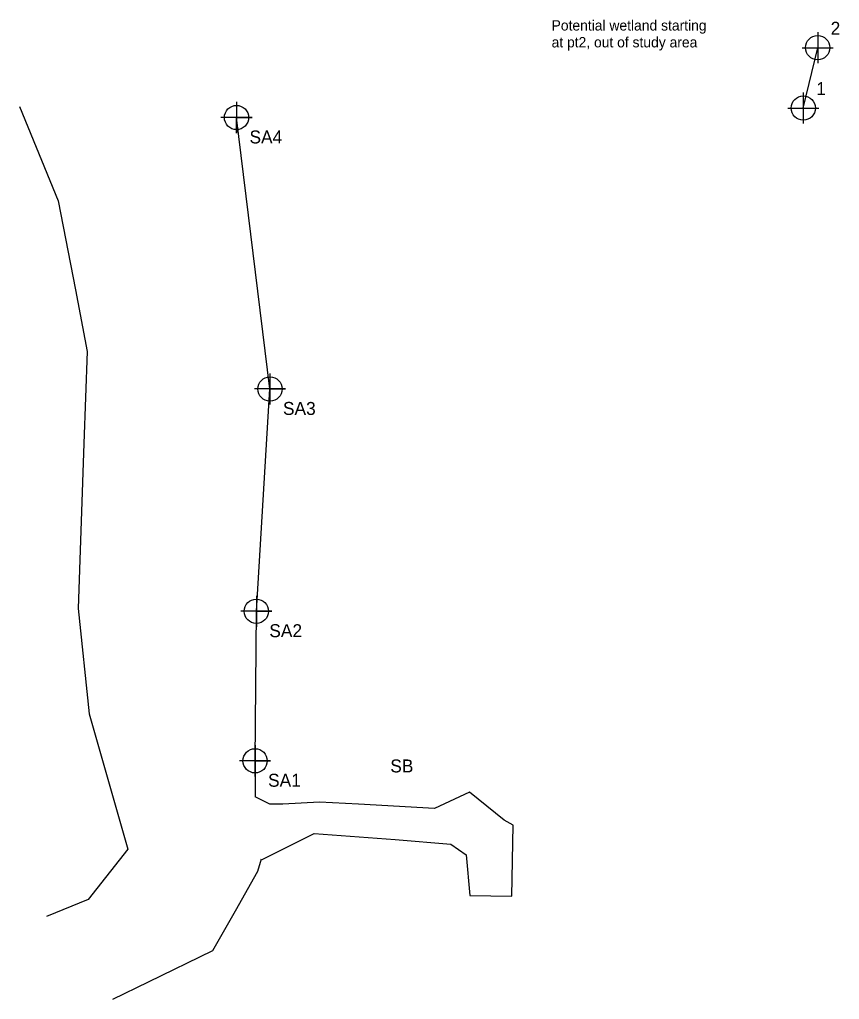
# Model space of a CAD drawing. Extents: x 2159473 to 2159631, y 1006206 to 1006395.
import ezdxf

# ---------------------------------------------------------------- set-up
doc = ezdxf.new("R2010")
doc.units = 0
for name, color, linetype in [('COGO Default Chain', 7, 'Continuous'), ('Cogo Default Point CELL', 7, 'Continuous'), ('COGO Default Point Number', 7, 'Continuous'), ('Exist Hydro Jurisdictional Stream or Body of Water NEU Mitigable', 7, 'Continuous'), ('Exist Hydro Jurisdictional Stream or Body of Water NEU Mitigable Cogo Comment', 7, 'Continuous'), ('Exist Hydro Jurisdictional Stream or Body of Water NEU Mitigable Cogo Point CELL', 7, 'Continuous'), ('Exist Hydro Jurisdictional Stream or Body of Water NEU NonMitigable', 7, 'Continuous')]:
    doc.layers.add(name, color=color, linetype=linetype)

msp = doc.modelspace()

# ---------------------------------------------------------------- linework, layer by layer
at = {"layer": 'COGO Default Chain'}
msp.add_line((2159623.64, 1006377.7), (2159626.42, 1006389.34), dxfattribs=at)
at = {"layer": 'Cogo Default Point CELL'}
for points in [[(2159626.42, 1006392.34), (2159626.42, 1006389.34)], [(2159623.42, 1006389.34), (2159626.42, 1006389.34)], [(2159626.42, 1006389.34), (2159629.42, 1006389.34)], [(2159626.42, 1006389.34), (2159626.42, 1006386.34)], [(2159623.64, 1006380.7), (2159623.64, 1006377.7)], [(2159620.64, 1006377.7), (2159623.64, 1006377.7)], [(2159623.64, 1006377.7), (2159626.64, 1006377.7)], [(2159623.64, 1006377.7), (2159623.64, 1006374.7)]]:
    msp.add_lwpolyline(points, dxfattribs=at)
for centre in [(2159626.42, 1006389.34), (2159623.64, 1006377.7)]:
    msp.add_circle(centre, 2.34, dxfattribs=at)
at = {"layer": 'Exist Hydro Jurisdictional Stream or Body of Water NEU Mitigable'}
for points in [[(2159472.52, 1006378), (2159479.96, 1006359.8), (2159483.27, 1006342.63), (2159485.55, 1006330.79), (2159484.92, 1006313.04), (2159483.8, 1006281.21), (2159485.96, 1006260.91), (2159489.68, 1006247.88), (2159493.4, 1006234.84)], [(2159517.93, 1006251.85), (2159518.17, 1006280.69), (2159520.8, 1006323.54), (2159514.35, 1006375.88)], [(2159517.93, 1006251.85), (2159517.93, 1006244.9)], [(2159493.4, 1006234.84), (2159485.75, 1006225.12), (2159477.69, 1006221.81)], [(2159519.1, 1006232.88), (2159518.42, 1006230.5), (2159514.08, 1006222.84), (2159509.74, 1006215.19), (2159497.33, 1006209.19), (2159490.42, 1006205.85)]]:
    msp.add_lwpolyline(points, dxfattribs=at)
at = {"layer": 'Exist Hydro Jurisdictional Stream or Body of Water NEU Mitigable Cogo Point CELL'}
for points in [[(2159514.35, 1006378.88), (2159514.35, 1006372.88), (2159514.35, 1006375.88), (2159517.35, 1006375.88), (2159511.35, 1006375.88)], [(2159520.8, 1006326.54), (2159520.8, 1006320.54), (2159520.8, 1006323.54), (2159523.8, 1006323.54), (2159517.8, 1006323.54)], [(2159518.17, 1006283.69), (2159518.17, 1006277.69), (2159518.17, 1006280.69), (2159521.17, 1006280.69), (2159515.17, 1006280.69)], [(2159517.93, 1006254.85), (2159517.93, 1006248.85), (2159517.93, 1006251.85), (2159520.93, 1006251.85), (2159514.93, 1006251.85)]]:
    msp.add_lwpolyline(points, dxfattribs=at)
for centre in [(2159514.35, 1006375.88), (2159520.8, 1006323.54), (2159518.17, 1006280.69), (2159517.93, 1006251.85)]:
    msp.add_circle(centre, 2.34, dxfattribs=at)
at = {"layer": 'Exist Hydro Jurisdictional Stream or Body of Water NEU NonMitigable'}
msp.add_lwpolyline([(2159519.27, 1006232.84), (2159529.34, 1006237.82), (2159544.91, 1006236.69), (2159555.67, 1006235.81), (2159558.63, 1006233.7), (2159559.33, 1006225.89), (2159567.45, 1006225.76), (2159567.67, 1006239.44), (2159565.99, 1006240.4), (2159559.3, 1006245.79), (2159552.54, 1006242.68), (2159537.88, 1006243.48), (2159530.33, 1006243.89), (2159523.28, 1006243.48), (2159520.75, 1006243.46), (2159517.93, 1006244.9)], dxfattribs=at)

# ---------------------------------------------------------------- texts
at = {"layer": 'COGO Default Point Number'}
for s, p in [('2', (2159628.92, 1006391.84)), ('1', (2159626.14, 1006380.2))]:
    msp.add_text(s, height=2.5, dxfattribs=at).set_placement(p)
at = {"layer": 'Exist Hydro Jurisdictional Stream or Body of Water NEU Mitigable'}
for s, p in [('Potential wetland starting ', (2159575.11, 1006392.65)), ('at pt2, out of study area', (2159575.11, 1006389.4))]:
    msp.add_text(s, height=2, dxfattribs=at).set_placement(p)
at = {"layer": 'Exist Hydro Jurisdictional Stream or Body of Water NEU Mitigable Cogo Comment'}
for s, p in [('SA4', (2159516.85, 1006370.88)), ('SA4', (2159516.85, 1006370.88)), ('SA4', (2159516.85, 1006370.88)), ('SA3', (2159523.3, 1006318.54)), ('SA2', (2159520.67, 1006275.69)), ('SB', (2159544, 1006249.61)), ('SA1', (2159520.43, 1006246.85))]:
    msp.add_text(s, height=2.5, dxfattribs=at).set_placement(p)

doc.saveas('drawing.dxf')
